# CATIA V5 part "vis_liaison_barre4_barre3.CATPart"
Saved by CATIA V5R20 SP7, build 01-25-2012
Part number: skl_vis_liaison_barre4_barre3
Bounding box of the stored display mesh (mm): x -2 to 22, y 3.165 to 3.165, z 6.187 to 6.187
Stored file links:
  J:\IFMA\IAO\système avant mef\vis_liaison_barre4_barre3.CATPart
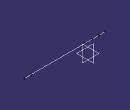
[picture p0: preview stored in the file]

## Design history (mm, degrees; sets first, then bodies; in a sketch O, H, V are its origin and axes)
Body1 (main body)
  Point1 "Point.Dprim": stored without definition
  Point2 "Point.D": stored without definition
  Point3 "Point_D_vis": stored without definition
  Point4 "Point.Dprim": stored without definition
  Line1: type PtPt, FirstPoint Point3, SecondPoint Point4
  Plane1 "Plan_ref": stored without definition
  Point5 "Point.D": stored without definition
  Line2 "axe_liaison_barre4_barre3": type Normal, RefPoint Point5, RefSkin Plane1, Start 0, End 20
  Plane2: stored without definition
  Point6 "Point.Dprim": stored without definition
  Line3 "axe_liaison_barre3_barre4": type Normal, RefPoint Point6, RefSkin Plane2, Start 0, End 20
